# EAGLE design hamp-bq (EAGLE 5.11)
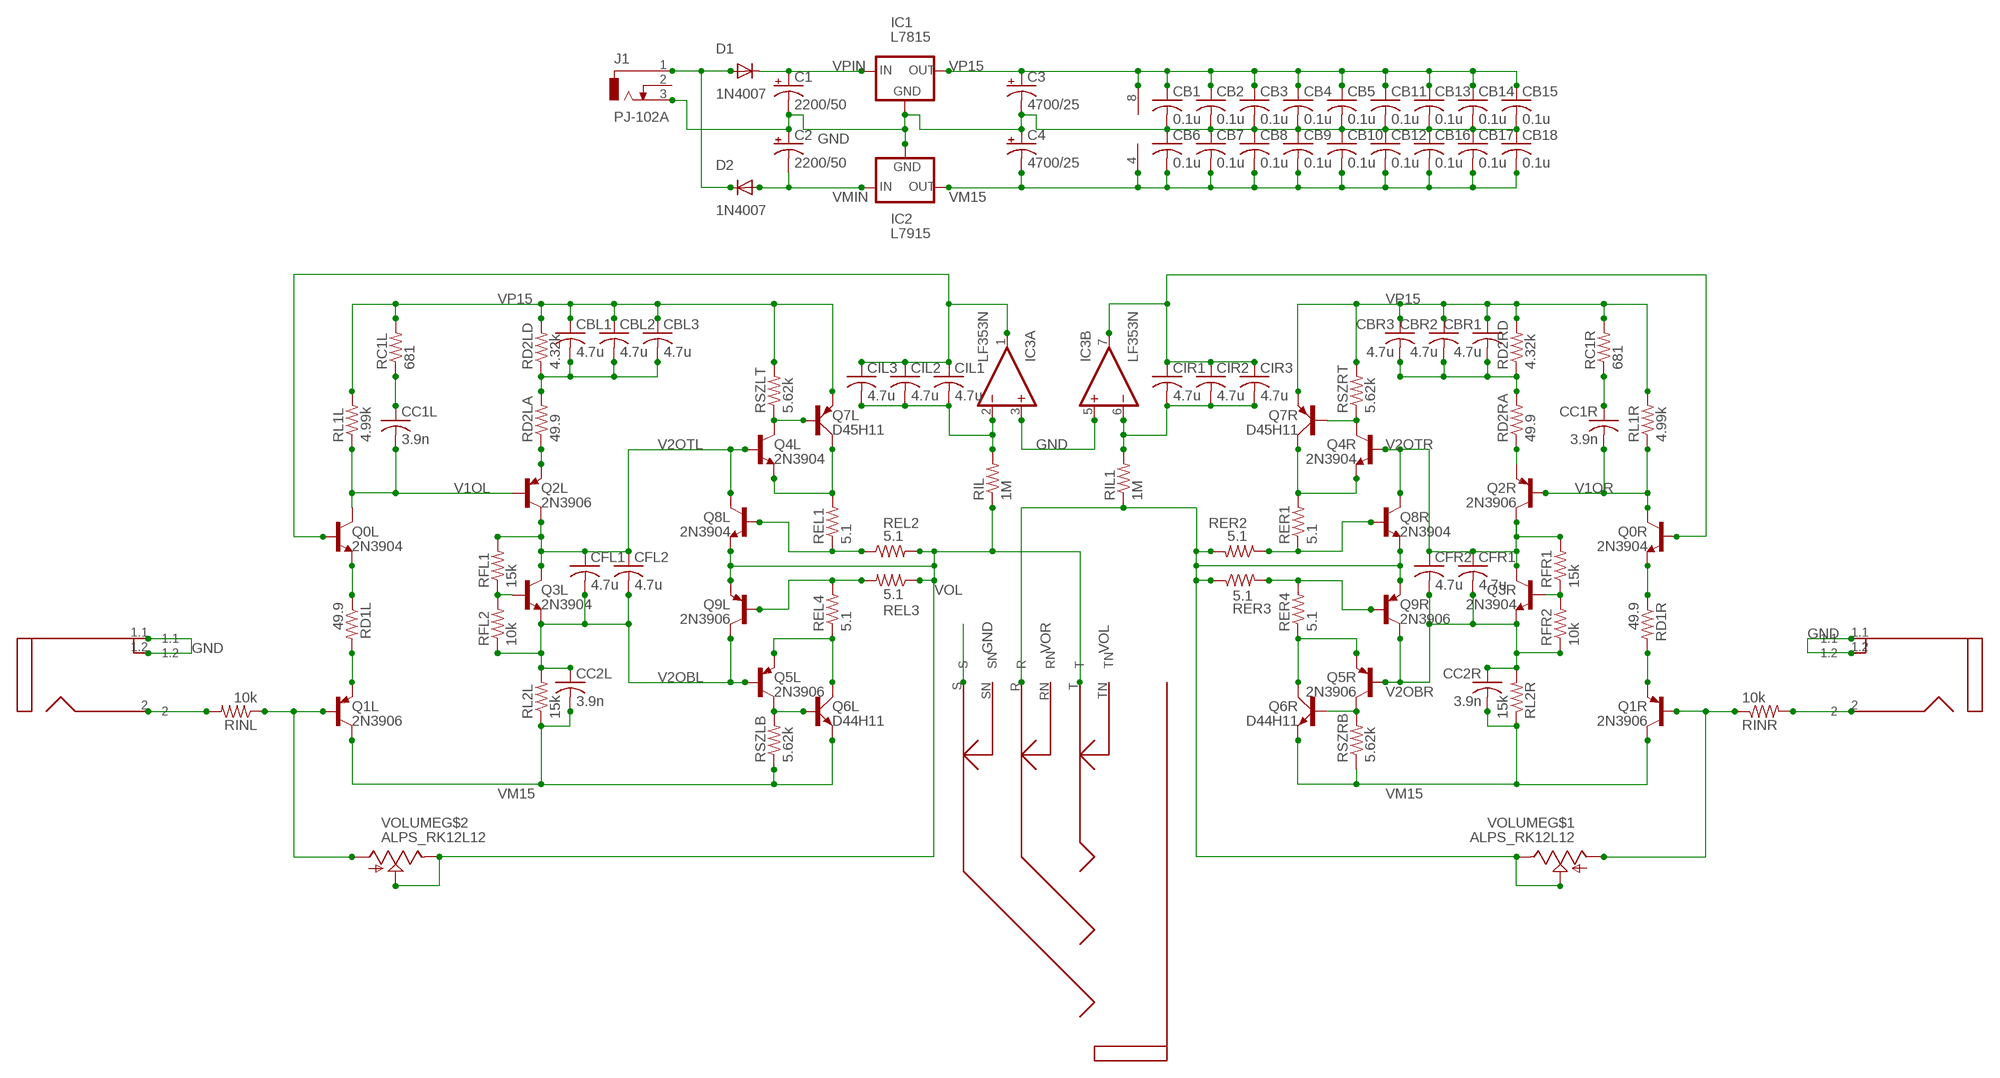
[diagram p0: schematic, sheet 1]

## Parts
C1  2200/50  CPOL-USE7.5-16  [E7,5-16]
C2  2200/50  CPOL-USE7.5-16  [E7,5-16]
C3  4700/25  CPOL-USE7.5-16  [E7,5-16]
C4  4700/25  CPOL-USE7.5-16  [E7,5-16]
CB1  0.1u  C-US025-025X050  [C025-025X050]
CB2  0.1u  C-US025-025X050  [C025-025X050]
CB3  0.1u  C-US025-025X050  [C025-025X050]
CB4  0.1u  C-US025-025X050  [C025-025X050]
CB5  0.1u  C-US025-025X050  [C025-025X050]
CB6  0.1u  C-US025-025X050  [C025-025X050]
CB7  0.1u  C-US025-025X050  [C025-025X050]
CB8  0.1u  C-US025-025X050  [C025-025X050]
CB9  0.1u  C-US025-025X050  [C025-025X050]
CB10  0.1u  C-US025-025X050  [C025-025X050]
CB11  0.1u  C-US025-025X050  [C025-025X050]
CB12  0.1u  C-US025-025X050  [C025-025X050]
CB13  0.1u  C-US025-025X050  [C025-025X050]
CB14  0.1u  C-US025-025X050  [C025-025X050]
CB15  0.1u  C-US025-025X050  [C025-025X050]
CB16  0.1u  C-US025-025X050  [C025-025X050]
CB17  0.1u  C-US025-025X050  [C025-025X050]
CB18  0.1u  C-US025-025X050  [C025-025X050]
CBL1  4.7u  C-US050-035X075  [C050-035X075]
CBL2  4.7u  C-US050-035X075  [C050-035X075]
CBL3  4.7u  C-US050-035X075  [C050-035X075]
CBR1  4.7u  C-US050-035X075  [C050-035X075]
CBR2  4.7u  C-US050-035X075  [C050-035X075]
CBR3  4.7u  C-US050-035X075  [C050-035X075]
CC1L  3.9n  C-US025-025X050  [C025-025X050]
CC1R  3.9n  C-US025-025X050  [C025-025X050]
CC2L  3.9n  C-US025-025X050  [C025-025X050]
CC2R  3.9n  C-US025-025X050  [C025-025X050]
CFL1  4.7u  C-US050-035X075  [C050-035X075]
CFL2  4.7u  C-US050-035X075  [C050-035X075]
CFR1  4.7u  C-US050-035X075  [C050-035X075]
CFR2  4.7u  C-US050-035X075  [C050-035X075]
CIL1  4.7u  C-US050-035X075  [C050-035X075]
CIL2  4.7u  C-US050-035X075  [C050-035X075]
CIL3  4.7u  C-US050-035X075  [C050-035X075]
CIR1  4.7u  C-US050-035X075  [C050-035X075]
CIR2  4.7u  C-US050-035X075  [C050-035X075]
CIR3  4.7u  C-US050-035X075  [C050-035X075]
D1  1N4007  1N4004  [DO41-10]
D2  1N4007  1N4004  [DO41-10]
IC1  L7815  78XXS  [78XXS]
IC2  L7915  79XXS  [79XXS]
IC3  LF353N  [DIL08]
J1  PJ-102A  DCJ0303  [DCJ0303]
Q0L  2N3904  [TO92]
Q0R  2N3904  [TO92]
Q1L  2N3906  [TO92]
Q1R  2N3906  [TO92]
Q2L  2N3906  [TO92]
Q2R  2N3906  [TO92]
Q3L  2N3904  [TO92]
Q3R  2N3904  [TO92]
Q4L  2N3904  [TO92]
Q4R  2N3904  [TO92]
Q5L  2N3906  [TO92]
Q5R  2N3906  [TO92]
Q6L  D44H11  MJE3055  [TO220AV]
Q6R  D44H11  MJE3055  [TO220AV]
Q7L  D45H11  MJE2955  [TO220AV]
Q7R  D45H11  MJE2955  [TO220AV]
Q8L  2N3904  [TO92]
Q8R  2N3904  [TO92]
Q9L  2N3906  [TO92]
Q9R  2N3906  [TO92]
RC1L  681  R-US_0309/V  [0309V]
RC1R  681  R-US_0309/V  [0309V]
RD1L  49.9  R-US_0309/V  [0309V]
RD1R  49.9  R-US_0309/V  [0309V]
RD2LA  49.9  R-US_0309/V  [0309V]
RD2LD  4.32k  R-US_0309/V  [0309V]
RD2RA  49.9  R-US_0309/V  [0309V]
RD2RD  4.32k  R-US_0309/V  [0309V]
REL1  5.1  R-US_0309/V  [0309V]
REL2  5.1  R-US_0309/V  [0309V]
REL3  5.1  R-US_0309/V  [0309V]
REL4  5.1  R-US_0309/V  [0309V]
RER1  5.1  R-US_0309/V  [0309V]
RER2  5.1  R-US_0309/V  [0309V]
RER3  5.1  R-US_0309/V  [0309V]
RER4  5.1  R-US_0309/V  [0309V]
RFL1  15k  R-US_0309/V  [0309V]
RFL2  10k  R-US_0309/V  [0309V]
RFR1  15k  R-US_0309/V  [0309V]
RFR2  10k  R-US_0309/V  [0309V]
RIL  1M  R-US_0309/V  [0309V]
RIL1  1M  R-US_0309/V  [0309V]
RINL  10k  R-US_0309/V  [0309V]
RINR  10k  R-US_0309/V  [0309V]
RL1L  4.99k  R-US_0309/V  [0309V]
RL1R  4.99k  R-US_0309/V  [0309V]
RL2L  15k  R-US_0309/V  [0309V]
RL2R  15k  R-US_0309/V  [0309V]
RSZLB  5.62k  R-US_0309/V  [0309V]
RSZLT  5.62k  R-US_0309/V  [0309V]
RSZRB  5.62k  R-US_0309/V  [0309V]
RSZRT  5.62k  R-US_0309/V  [0309V]
U$1  NJ6H?D2  [NMJ6H?D2]
U$2  RCA-VERT  [RCA]
U$3  RCA-VERT  [RCA]
VOLUME  ALPS_RK12L12  [RK12L12C]

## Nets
GND [supply]: C1.- C2.+ C3.- C4.+ CB1.2 CB2.2 CB3.2 CB4.2 CB5.2 CB6.1 CB7.1 CB8.1 CB9.1 CB10.1 CB11.2 CB12.1 CB13.2 CB14.2 CB15.2 CB16.1 CB17.1 CB18.1 IC1.GND IC2.GND IC3.3(A:+IN) IC3.5(B:+IN) J1.3 U$1.S U$2.1.1 U$2.1.2 U$3.1.1 U$3.1.2
N$1 [supply]: D1.A D2.C J1.1
N$6: Q0L.3(E) RD1L.1
N$7: Q1L.3(E) RD1L.2
N$8: CC1L.1 RC1L.1
N$9: CIL1.2 CIL2.2 CIL3.2 IC3.2(A:-IN) RIL.2
N$10: Q1L.2(B) RINL.1 VOLUME.2.1(A)
N$11: Q4L.1(C) Q7L.B RSZLT.1
N$12: Q5L.1(C) Q6L.B RSZLB.2
N$13: CBL1.2 CBL2.2 CBL3.2 RD2LA.2 RD2LD.1
N$14: Q2L.3(E) RD2LA.1
N$15: Q3L.2(B) RFL1.1 RFL2.2
N$16: CIL1.1 CIL2.1 CIL3.1 IC3.1(A:OUT) Q0L.2(B)
N$17: RINL.2 U$2.2
N$18: Q9L.2(B) REL3.2 REL4.2
N$19 [power]: Q5L.3(E) Q6L.C REL4.1
N$20 [power]: Q4L.3(E) Q7L.C REL1.2
N$21: Q8L.2(B) REL1.1 REL2.1
N$22: CIR1.1 CIR2.1 CIR3.1 IC3.7(B:OUT) Q0R.2(B)
N$23: CIR1.2 CIR2.2 CIR3.2 IC3.6(B:-IN) RIL1.2
N$25 [power]: Q5R.3(E) Q6R.C RER4.1
N$26: Q9R.2(B) RER3.2 RER4.2
N$27: CBR1.2 CBR2.2 CBR3.2 RD2RA.2 RD2RD.1
N$28: Q8R.2(B) RER1.1 RER2.1
N$29 [power]: Q4R.3(E) Q7R.C RER1.2
N$30: Q4R.1(C) Q7R.B RSZRT.1
N$31: Q0R.3(E) RD1R.1
N$32: Q2R.3(E) RD2RA.1
N$33: Q1R.3(E) RD1R.2
N$34: CC1R.1 RC1R.1
N$35: Q5R.1(C) Q6R.B RSZRB.2
N$37: Q3R.2(B) RFR1.1 RFR2.2
N$38: Q1R.2(B) RINR.1 VOLUME.1.1(A)
N$39: RINR.2 U$3.2
V1OL: CC1L.2 Q0L.1(C) Q2L.2(B) RL1L.1
V1OR: CC1R.2 Q0R.1(C) Q2R.2(B) RL1R.1
V2OBL: CC2L.1 CFL1.2 CFL2.2 Q3L.3(E) Q5L.2(B) Q9L.1(C) RFL2.1 RL2L.2
V2OBR: CC2R.1 CFR1.2 CFR2.2 Q3R.3(E) Q5R.2(B) Q9R.1(C) RFR2.1 RL2R.2
V2OTL: CFL1.1 CFL2.1 Q2L.1(C) Q3L.1(C) Q4L.2(B) Q8L.1(C) RFL1.2
V2OTR: CFR1.1 CFR2.1 Q2R.1(C) Q3R.1(C) Q4R.2(B) Q8R.1(C) RFR1.2
VM15 [supply]: C4.- CB6.2 CB7.2 CB8.2 CB9.2 CB10.2 CB12.2 CB16.2 CB17.2 CB18.2 CC2L.2 CC2R.2 IC2.OUT IC3.4(P:V-) Q1L.1(C) Q1R.1(C) Q6L.E Q6R.E RL2L.1 RL2R.1 RSZLB.1 RSZRB.1
VMIN [supply]: C2.- D2.A IC2.IN
VOL [power]: Q8L.3(E) Q9L.3(E) REL2.2 REL3.1 RIL.1 U$1.T VOLUME.2.2(S) VOLUME.2.3(E)
VOR [power]: Q8R.3(E) Q9R.3(E) RER2.2 RER3.1 RIL1.1 U$1.R VOLUME.1.2(S) VOLUME.1.3(E)
VP15 [supply]: C3.+ CB1.1 CB2.1 CB3.1 CB4.1 CB5.1 CB11.1 CB13.1 CB14.1 CB15.1 CBL1.1 CBL2.1 CBL3.1 CBR1.1 CBR2.1 CBR3.1 IC1.OUT IC3.8(P:V+) Q7L.E Q7R.E RC1L.2 RC1R.2 RD2LD.2 RD2RD.2 RL1L.2 RL1R.2 RSZLT.2 RSZRT.2
VPIN [supply]: C1.+ D1.C IC1.IN
Unconnected: J1.2 U$1.RN U$1.SN U$1.TN

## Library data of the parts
C1-C4 = rcl:CPOL-US: POLARIZED CAPACITOR, American symbol
CB1-CB18 CBL1-CBL3 CBR1-CBR3 CC1L CC1R CC2L CC2R CFL1 CFL2 CFR1 CFR2 CIL1-CIL3 CIR1-CIR3 = rcl:C-US: CAPACITOR, American symbol
D1 D2 = diode:1N4004: DIODE
IC1 = v-reg:78XXS: VOLTAGE REGULATOR
IC2 = v-reg:79XXS: VOLTAGE REGULATOR
IC3 = linear:LF353: OP AMP
J1 = con-jack:DCJ0303: DC POWER JACK Source: DCJ0303.pdf; OC_FARNELL: unknown; OC_NEWARK: unknown
Q0L Q0R Q3L Q3R Q4L Q4R Q8L Q8R = transistor:2N3904: NPN TRANSISTOR
Q1L Q1R Q2L Q2R Q5L Q5R Q9L Q9R = transistor-pnp:2N3906: PNP Transistor
Q6L Q6R = transistor-power:MJE3055: NPN TRANSISTOR
Q7L Q7R = transistor-power:MJE2955: PNP TRANSISTOR
RC1L RC1R RD1L RD1R RD2LA RD2LD RD2RA RD2RD REL1-REL4 RER1-RER4 RFL1 RFL2 RFR1 RFR2 RIL RIL1 RINL RINR RL1L RL1R RL2L RL2R RSZLB RSZLT RSZRB RSZRT = rcl:R-US_: RESISTOR, American symbol
U$1 = con-neutrik_ag:NJ6: Neutrik NJ6* stereo 1/4" audio jack
U$2 U$3 = con-cui:RCA-VERT
VOLUME = pot:ALPS_RK12L12

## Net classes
0 default: width 0.406 mm, clearance 0.203 mm
1 power: width 0.762 mm, clearance 0.381 mm
2 supply: width 1.27 mm, clearance 0.381 mm

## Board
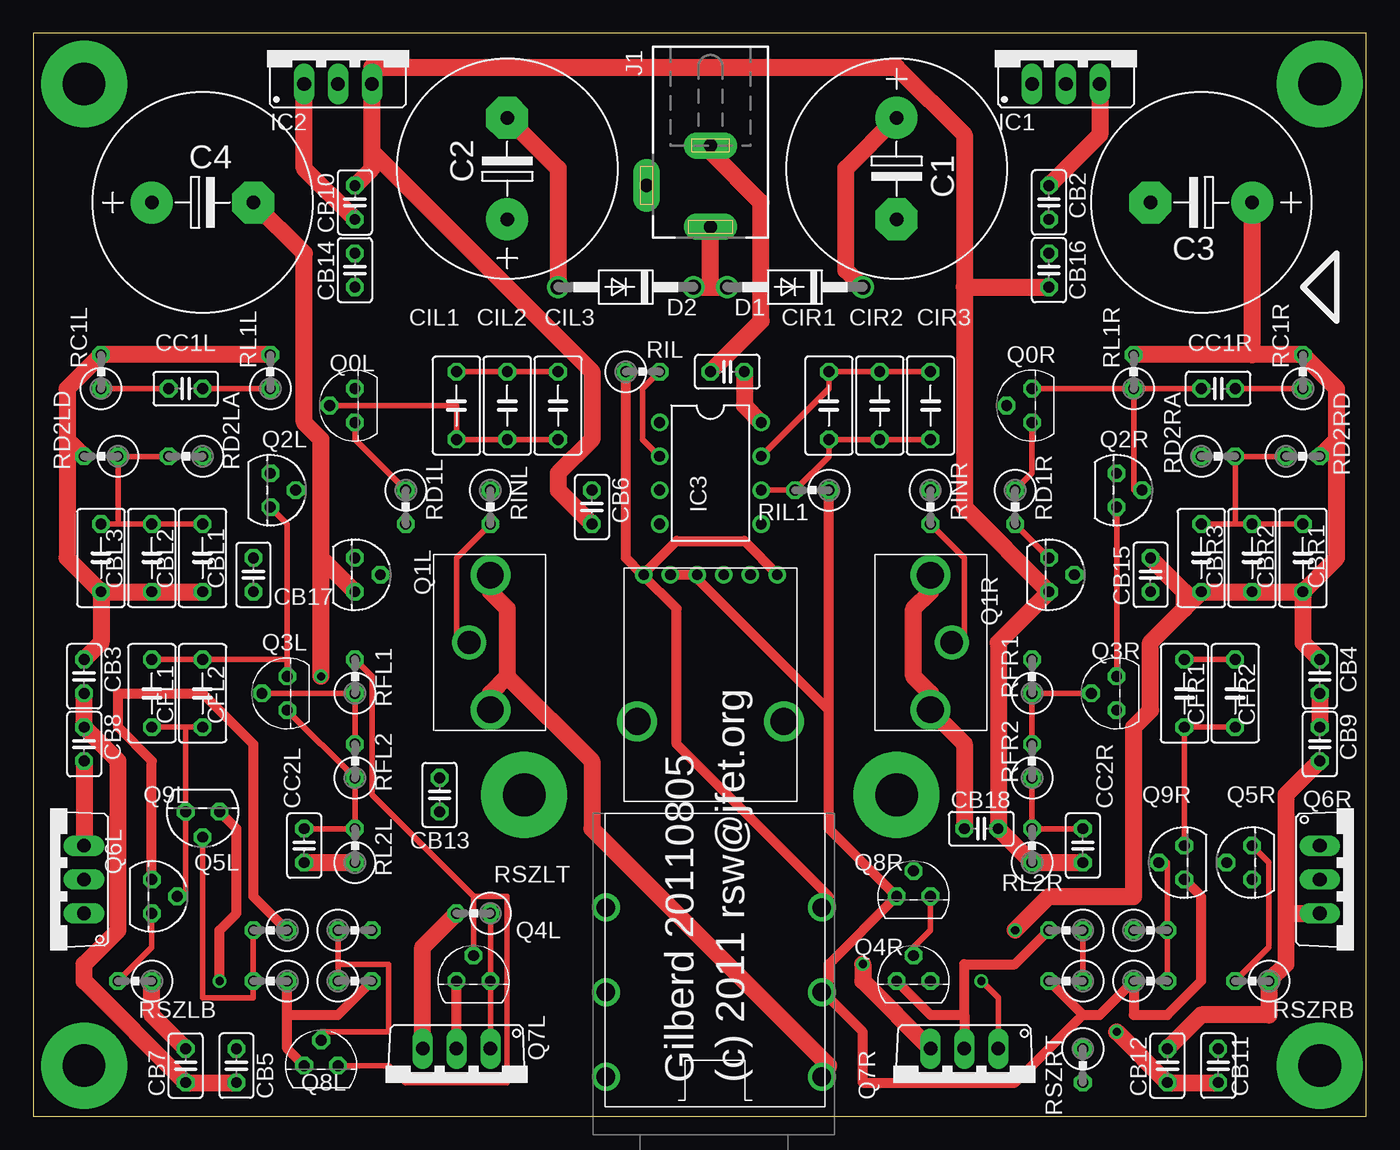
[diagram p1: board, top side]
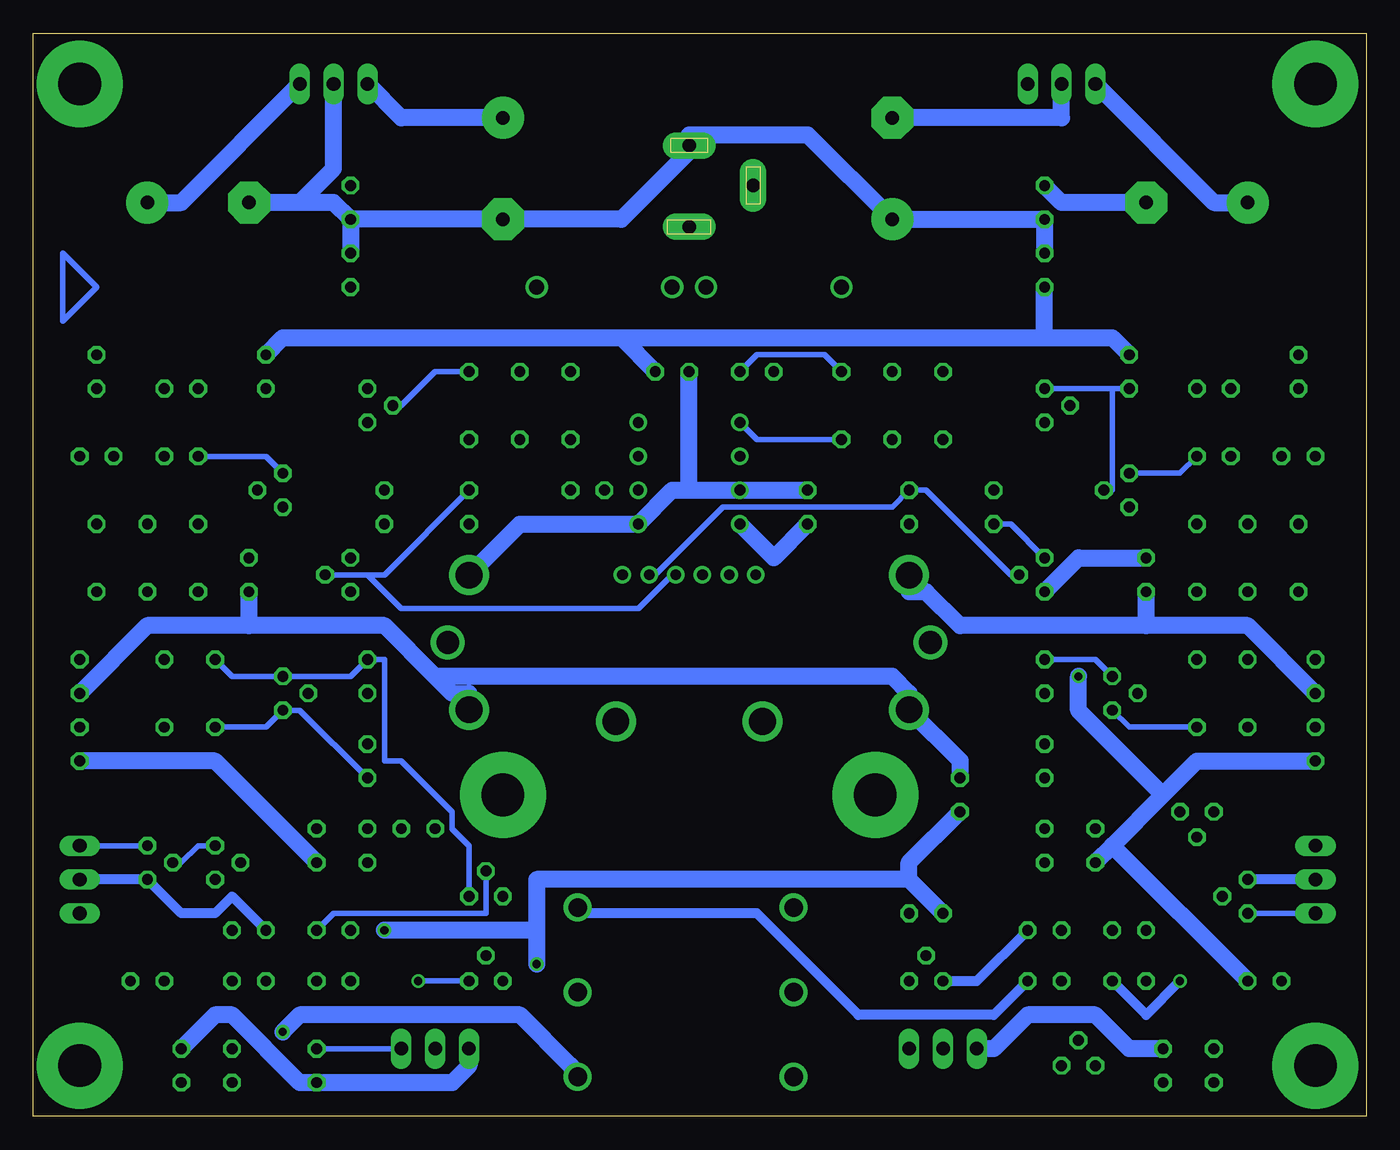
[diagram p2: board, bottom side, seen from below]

Size 100 x 81.27 mm. Coordinates in mm from the lower left corner, seen from the top.
Outline: 0,0 100,0 100,81.27 0,81.27 0,0
Copper layers (1*16): Top 0.035mm / dielectric 1.5mm / Bottom 0.035mm
Design rules "default": minimum track width 10mil, minimum drill 24mil, track to track 8mil, track to pad 8mil, pad to pad 8mil, via to via 8mil, smd to smd 8mil, copper to edge 40mil, drill to drill 8mil, minimum pad ring 10mil, minimum via ring 8mil, stop-mask expansion 4mil, vias tented up to drill 0mil, thermal gap 10mil

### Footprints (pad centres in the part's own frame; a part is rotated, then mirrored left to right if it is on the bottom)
E7,5-16 = drill 1.016 pad 3.15 round: + -3.81,0 | drill 1.016 pad 3.15 octagon: - 3.81,0
C025-025X050 = drill 0.813 octagon: 1 -1.27,0; 2 1.27,0
C050-035X075 = drill 0.813 octagon: 1 -2.54,0; 2 2.54,0
DO41-10 = drill 1.118 round: A 5.08,0; C -5.08,0
78XXS = drill 1.016 long: GND 0,-2.54; IN -2.54,-2.54; OUT 2.54,-2.54
79XXS = drill 1.016 long: GND -2.54,-2.54; IN 0,-2.54; OUT 2.54,-2.54
DIL08 = drill 0.813 pad 1.27 round: 1 -3.81,-3.81; 2 -1.27,-3.81; 3 1.27,-3.81; 4 3.81,-3.81; 5 3.81,3.81; 6 1.27,3.81; 7 -1.27,3.81; 8 -3.81,3.81
DCJ0303 = drill 1 pad 2 long: 1 0,3.1; 2 4.8,0; 3 0,-3
TO92 = drill 0.813 octagon: 1 1.27,0; 2 0,1.905; 3 -1.27,0
TO220AV = drill 1.016 long: B -2.54,-2.54; C 0,-2.54; E 2.54,-2.54
0309V = drill 0.813 octagon: 1 -1.27,0; 2 1.27,0
NMJ6H?D2 = drill 1.4 round: R 17.25,10.6; RN 1.05,10.6; S 17.25,4.25; SN 1.05,4.25; T 17.25,16.95; TN 1.05,16.95
RCA = drill 2 round: 1.1 -5.05,0; 1.2 5.05,0 | drill 1.7 round: 2 0,1.6
RK12L12C = drill 0.8 round: 1.1 -1,0; 1.2 1,0; 1.3 3,0; 2.1 -3,0; 2.2 -5,0; 2.3 5,0 | drill 2 round: CASE1 -5.5,11; CASE2 5.5,11

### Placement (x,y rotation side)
C1  64.77,71.12 270 top
C2  35.56,71.12 90 top
C3  87.63,68.58 180 top
C4  12.7,68.58 0 top
CB1  52.07,55.88 180 top
CB2  76.2,68.58 270 top
CB3  3.81,33.02 270 top
CB4  96.52,33.02 270 top
CB5  15.24,3.81 270 top
CB6  41.91,45.72 270 top
CB7  11.43,3.81 90 top
CB8  3.81,27.94 270 top
CB9  96.52,27.94 270 top
CB10  24.13,68.58 90 top
CB11  88.9,3.81 270 top
CB12  85.09,3.81 90 top
CB13  30.48,24.13 90 top
CB14  24.13,63.5 90 top
CB15  83.82,40.64 270 top
CB16  76.2,63.5 270 top
CB17  16.51,40.64 90 top
CB18  71.12,21.59 0 top
CBL1  12.7,41.91 90 top
CBL2  8.89,41.91 90 top
CBL3  5.08,41.91 90 top
CBR1  95.25,41.91 90 top
CBR2  91.44,41.91 90 top
CBR3  87.63,41.91 90 top
CC1L  11.43,54.61 0 top
CC1R  88.9,54.61 180 top
CC2L  20.32,20.32 270 top
CC2R  78.74,20.32 270 top
CFL1  8.89,31.75 270 top
CFL2  12.7,31.75 270 top
CFR1  86.36,31.75 270 top
CFR2  90.17,31.75 270 top
CIL1  31.75,53.34 90 top
CIL2  35.56,53.34 90 top
CIL3  39.37,53.34 90 top
CIR1  59.69,53.34 270 top
CIR2  63.5,53.34 270 top
CIR3  67.31,53.34 270 top
D1  57.15,62.23 180 top
D2  44.45,62.23 180 top
IC1  77.47,80.01 0 top
IC2  22.86,80.01 0 top
IC3  50.8,48.26 270 top
J1  50.8,69.85 180 top
Q0L  24.13,53.34 90 top
Q0R  74.93,53.34 90 top
Q1L  24.13,40.64 270 top
Q1R  76.2,40.64 270 top
Q2L  17.78,46.99 270 top
Q2R  81.28,46.99 270 top
Q3L  19.05,31.75 90 top
Q3R  81.28,31.75 90 top
Q4L  33.02,10.16 0 top
Q4R  66.04,10.16 0 top
Q5L  8.89,16.51 270 top
Q5R  91.44,19.05 90 top
Q6L  1.27,17.78 90 top
Q6R  99.06,17.78 270 top
Q7L  31.75,2.54 180 top
Q7R  69.85,2.54 180 top
Q8L  21.59,3.81 0 top
Q8R  66.04,16.51 0 top
Q9L  12.7,22.86 180 top
Q9R  86.36,19.05 90 top
RC1L  5.08,55.88 90 top
RC1R  95.25,55.88 90 top
RD1L  27.94,45.72 270 top
RD1R  73.66,45.72 270 top
RD2LA  11.43,49.53 180 top
RD2LD  5.08,49.53 180 top
RD2RA  88.9,49.53 0 top
RD2RD  95.25,49.53 0 top
REL1  24.13,13.97 0 top
REL2  24.13,10.16 0 top
REL3  17.78,10.16 180 top
REL4  17.78,13.97 180 top
RER1  77.47,13.97 180 top
RER2  77.47,10.16 180 top
RER3  83.82,10.16 0 top
RER4  83.82,13.97 0 top
RFL1  24.13,33.02 90 top
RFL2  24.13,26.67 90 top
RFR1  74.93,33.02 90 top
RFR2  74.93,26.67 90 top
RIL  45.72,55.88 0 top
RIL1  58.42,46.99 180 top
RINL  34.29,45.72 270 top
RINR  67.31,45.72 270 top
RL1L  17.78,55.88 90 top
RL1R  82.55,55.88 90 top
RL2L  24.13,20.32 90 top
RL2R  74.93,20.32 90 top
RSZLB  7.62,10.16 180 top
RSZLT  33.02,15.24 180 top
RSZRB  91.44,10.16 180 top
RSZRT  78.74,3.81 270 top
U$1  41.91,-1.27 0 top
U$2  34.29,35.56 90 top
U$3  67.31,35.56 270 top
VOLUME  50.8,40.64 180 top

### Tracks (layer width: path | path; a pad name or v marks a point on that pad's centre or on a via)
GND  (via drill 0.61)
  Top 1.27: CB11.2 CB12.1 v81.28,6.35 | CB5.2 CB7.1 3.81,10.16 3.81,11.43 6.35,13.97 6.35,26.67 CB8.1 CB3.2 | 35.56,33.02 34.29,31.75 U$2.1.1 | 35.56,33.02 35.56,38.1 34.29,39.37 U$2.1.2 | 35.56,33.02 41.91,26.67 41.91,21.59 59.69,3.81 U$1.S | CB4.2 CB9.1 | U$3.1.1 67.31,39.37 66.04,38.1 66.04,33.02 67.31,31.75 U$3.1.2 69.85,27.97 CB18.1 | CB10.1 20.32,71.12 IC2.GND | CB1.2 54.61,59.69 54.61,68.58 50.8,72.39 J1.3
  Bottom 1.27: v81.28,6.35 80.01,7.62 63.5,7.62 59.69,3.81 U$1.S | CB3.2 8.89,36.83 16.51,36.83 | 16.51,36.83 30.48,36.83 33.02,39.37 34.29,39.37 U$2.1.2 | CB4.2 91.44,36.83 83.82,36.83 | 83.82,36.83 73.66,36.83 69.85,33.02 | 69.85,33.02 68.58,31.75 67.31,31.75 U$3.1.2 | CB6.1 IC3.3 50.8,46.99 | 50.8,46.99 52.07,46.99 IC3.5 63.5,44.45 67.31,40.64 U$3.1.1 | 50.8,46.99 CB1.2 | IC2.GND 11.43,68.58 C4.+ | CB2.2 77.47,68.58 80.01,68.58 | 80.01,68.58 C3.- | IC1.GND 77.47,71.12 80.01,68.58 | CB2.2 C1.- 55.88,67.31 50.8,72.39 J1.3 50.8,73.66 41.91,73.66 C2.+ CB10.1 CB14.2 | 69.85,33.02 35.56,33.02 34.29,31.75 U$2.1.1 30.48,26.7 CB13.2 | CB2.2 CB16.1 | 16.51,36.83 CB17.1 | 83.82,36.83 CB15.2
N$1
  Top 1.27: 50.8,62.23 D1.A | D2.C 50.8,62.23 | 50.8,62.23 J1.1
N$2  (via drill 3.2 pad 6.45)
  other vias: 3.81,77.47
N$3  (via drill 3.2 pad 6.45)
  other vias: 36.83,24.13
N$4  (via drill 3.2 pad 6.45)
  other vias: 96.52,3.81
N$5  (via drill 3.2 pad 6.45)
  other vias: 3.81,3.81
N$6
  Top 0.406: RD1L.1 24.13,50.8 Q0L.3
N$7
  Bottom 0.406: Q1L.3 26.67,44.45 RD1L.2
N$8
  Top 0.406: RC1L.1 CC1L.1
N$9
  Top 0.406: IC3.2 45.72,50.8 45.72,54.61 RIL.2 | CIL1.2 CIL2.2 CIL3.2
  Bottom 0.406: RIL.2 45.72,57.15 40.64,57.15 CIL3.2
N$10
  Bottom 0.406: VOLUME.2.1 53.34,40.64 48.26,45.72 35.56,45.72 RINL.1 33.02,46.99 26.67,40.64 Q1L.2
N$11
  Top 0.406: RSZLT.1 Q4L.1 Q7L.B
N$12
  Top 0.406: RSZLB.2 8.89,12.7 Q5L.1
  Bottom 0.406: Q5L.1 Q6L.B
N$13
  Top 0.406: RD2LA.2 RD2LD.1 6.35,44.45 | 6.35,44.45 CBL2.2 CBL1.2 | CBL3.2 6.35,44.45
N$14
  Bottom 0.406: RD2LA.1 13.97,48.26 Q2L.3
N$15
  Top 0.406: Q3L.2 RFL1.1 RFL2.2
N$16
  Top 0.406: CIL3.1 CIL2.1 CIL1.1 31.75,53.34 Q0L.2
  Bottom 0.406: IC3.1 45.72,50.8 CIL3.1
N$17
  Top 0.406: RINL.2 31.75,41.91 31.75,35.56 U$2.2
N$18
  Top 0.406: REL4.2 REL3.2 16.51,8.89 12.7,8.89 Q9L.2
N$19
  Top 0.762: REL4.1 16.51,16.51 16.51,27.94 12.7,31.75 6.35,31.75 6.35,29.21 8.89,26.67 Q5L.3
  Bottom 0.762: Q6L.C Q5L.3
N$20
  Top 0.762: Q7L.C Q4L.3
  Bottom 0.762: REL1.2 29.21,10.16 Q4L.3
N$21
  Top 0.406: 22.86,11.43 26.67,11.43 26.67,6.35 21.59,6.35 Q8L.2 | 22.86,11.43 REL2.1 | 22.86,11.43 REL1.1
N$22
  Top 0.406: IC3.7 59.69,54.61 CIR1.1 CIR2.1 CIR3.1
  Bottom 0.406: CIR3.1 69.85,55.88 72.39,53.34 Q0R.2
N$23
  Top 0.406: IC3.6 RIL1.2 59.69,49.53 CIR1.2 CIR2.2 CIR3.2
N$24  (via drill 3.2 pad 6.45)
  other vias: 64.77,24.13
N$25
  Bottom 0.762: RER4.1 85.09,16.51 86.36,15.24 88.9,15.24 Q5R.3 Q6R.C
N$26
  Top 0.406: RER3.2 RER4.2 85.09,19.05 Q9R.2
N$27
  Top 0.406: RD2RD.1 RD2RA.2 90.17,44.45 | 90.17,44.45 CBR2.2 CBR1.2 | CBR3.2 90.17,44.45
N$28
  Top 0.406: RER1.1 RER2.1
  Bottom 0.406: RER1.1 77.47,15.24 66.04,15.24 Q8R.2
N$29
  Top 0.762: Q4R.3 67.31,7.62 69.85,7.62 | 69.85,7.62 Q7R.C | RER1.2 73.66,11.43 69.85,11.43 69.85,7.62
N$30  (via drill 0.61)
  Top 0.406: v71.12,10.16 72.39,8.89 Q7R.B
  Bottom 0.406: Q7R.B RSZRT.1 | Q4R.1 v71.12,10.16
N$31
  Top 0.406: RD1R.1 74.93,48.26 Q0R.3
N$32
  Bottom 0.406: Q2R.3 82.55,49.53 RD2RA.1
N$33
  Top 0.406: Q1R.3 RD1R.2
N$34
  Top 0.406: CC1R.1 RC1R.1
N$35
  Top 0.406: RSZRB.2 92.71,12.7 92.71,19.05 Q5R.1
  Bottom 0.406: Q5R.1 Q6R.B
N$36
  Bottom 0.406: 95.25,62.23 97.79,64.77 97.79,59.69 95.25,62.23
N$37
  Top 0.406: RFR2.2 RFR1.1 Q3R.2
N$38
  Bottom 0.406: 74.93,40.64 72.39,38.1 54.61,38.1 52.07,40.64 VOLUME.1.1 | 74.93,40.64 Q1R.2 | RINR.1 73.66,40.64 74.93,40.64
N$39
  Top 0.406: RINR.2 69.85,41.91 69.85,35.56 U$3.2
N$40
  Top 0.406: 95.25,62.23 97.79,64.77 97.79,59.69 95.25,62.23
NH1  (via drill 3.2 pad 6.45)
  other vias: 96.52,77.47
V1OL
  Top 0.406: RL1L.1 CC1L.2
  Bottom 0.406: 19.05,54.61 19.05,46.99 Q2L.2 | 19.05,54.61 RL1L.1 | 19.05,54.61 Q0L.1
V1OR
  Top 0.406: RL1R.1 Q0R.1 | RL1R.1 82.55,46.99 Q2R.2 | RL1R.1 CC1R.2
V2OBL
  Top 0.406: CC2L.1 RL2L.2 RFL2.1 Q3L.3 | Q5L.2 11.43,16.51 Q9L.1 11.43,29.21 | 11.43,29.21 CFL2.2 | 11.43,29.21 CFL1.2
  Bottom 0.406: Q3L.3 17.78,29.21 CFL2.2
V2OBR
  Top 0.406: RFR2.1 RL2R.2 CC2R.1 | CFR2.2 CFR1.2 Q9R.1
  Bottom 0.406: Q9R.1 87.63,20.32 88.9,19.05 Q5R.2 | CFR1.2 82.55,29.21 Q3R.3 80.01,30.48 RFR2.1
V2OTL
  Top 0.406: Q8L.1 26.67,3.81 27.94,2.54 35.56,2.54 35.56,16.51 33.02,16.51 | 33.02,16.51 Q4L.2 | CFL1.1 CFL2.1 19.05,34.29 | Q2L.1 19.05,44.45 19.05,34.29 | Q3L.1 19.05,34.29 | 33.02,16.51 25.4,24.13 25.4,33.02 RFL1.2
  Bottom 0.406: Q3L.1 20.32,34.29 RFL1.2
V2OTR
  Top 0.406: Q8R.1 67.31,13.97 66.04,12.7 Q4R.2 | CFR1.1 CFR2.1 | Q3R.1 Q2R.1
  Bottom 0.406: CFR1.1 85.09,33.02 Q3R.1 76.2,33.02 RFR1.2 73.66,34.29 73.66,26.67 72.39,26.67 68.58,22.86 68.58,21.59 67.31,20.32 Q8R.1
VM15  (via drill 0.61)
  Top 1.27: CC2R.2 RL2R.1 CB18.2 72.39,35.56 Q1R.1 69.85,45.72 69.85,62.23 | CB12.2 87.63,7.62 92.71,7.62 RSZRB.1 93.98,11.43 93.98,15.24 | CB9.2 93.98,24.13 93.98,15.24 | 93.98,15.24 Q6R.E | CB10.2 25.4,71.12 25.4,72.39 | 25.4,72.39 IC2.OUT 25.4,78.74 64.77,78.74 69.85,73.66 69.85,62.23 | CB6.2 39.37,46.99 39.37,48.26 41.91,50.8 41.91,55.88 25.4,72.39 | CB7.2 8.89,7.62 RSZLB.1 | CC2L.2 RL2L.1 | CB8.2 Q6L.E | 21.59,41.91 Q1L.1 | 21.59,41.91 21.59,50.8 20.32,52.07 20.32,64.77 C4.- | v21.59,33.02 21.59,41.91 | 69.85,62.23 CB16.2
  Bottom 1.27: CC2R.2 86.36,26.67 CB9.2 | CB6.2 44.45,41.91 IC3.4 | 15.24,24.13 12.7,26.67 CB8.2 | 19.05,20.32 15.24,24.13 | 19.05,20.32 CC2L.2 | RSZLB.1 19.05,20.32 | 15.24,24.13 21.59,30.48 v21.59,33.02 | CB10.2 22.86,68.58 C4.- | CB17.2 21.59,41.91 Q1L.1
VMIN
  Top 1.27: D2.A 39.37,71.12 C2.-
  Bottom 1.27: IC2.IN 22.86,74.93 C2.-
VOL  (via drill 0.61)
  Top 0.762: Q8L.3 19.05,5.08 19.05,7.62 | 19.05,7.62 REL3.1 | REL2.2 22.86,7.62 19.05,7.62 | Q9L.3 15.24,21.59 15.24,15.24 13.97,13.97 v13.97,10.16 | 45.72,40.64 44.45,41.91 RIL.1 | 45.72,40.64 48.26,43.18 53.34,43.18 55.88,40.64 VOLUME.2.2 | 45.72,40.64 48.26,38.1 48.26,27.94 59.69,16.51 U$1.T | 45.72,40.64 VOLUME.2.3
  Bottom 0.762: v13.97,10.16 16.51,7.62 REL3.1 | REL2.2 27.94,7.62 38.1,7.62 45.72,15.24 58.42,15.24 U$1.T
VOR
  Top 0.762: 78.74,7.62 RER2.2 | 78.74,7.62 80.01,7.62 RER3.1 82.55,7.62 85.09,7.62 87.63,10.16 87.63,16.51 Q9R.3 | 49.53,40.64 VOLUME.1.3 | 59.69,30.48 59.69,21.59 Q8R.3 59.69,11.43 59.69,10.16 U$1.R 59.69,8.89 62.23,6.35 62.23,2.54 73.66,2.54 78.74,7.62 | 59.69,30.48 RIL1.1 | 59.69,30.48 49.53,40.64 | 49.53,40.64 VOLUME.1.2
VP15  (via drill 0.61)
  Top 1.27: RSZLT.2 29.21,12.7 Q7L.E | Q7R.E 62.23,10.16 v62.23,11.43 | CB3.1 5.08,35.56 CBL3.1 | CBL3.1 CBL2.1 CBL1.1 | 2.54,50.8 RD2LD.2 | 2.54,50.8 2.54,54.61 RC1L.2 RL1L.2 | CBL3.1 2.54,41.91 2.54,50.8 | CBR1.1 CBR2.1 CBR3.1 86.36,38.1 | CB4.1 95.25,35.56 CBR1.1 | CB2.1 80.01,73.66 IC1.OUT | IC3.8 53.34,53.34 CB1.1 | 91.44,57.15 RC1R.2 97.79,54.61 97.79,50.8 | 91.44,57.15 RL1R.2 | 97.79,50.8 RD2RD.2 | 91.44,57.15 C3.+ | CBR1.1 97.79,41.91 97.79,50.8 | v73.66,13.97 76.2,16.51 82.55,16.51 82.55,29.21 83.82,30.48 83.82,35.56 86.36,38.1 | CB15.1 86.36,39.37 86.36,38.1
  Bottom 1.27: Q7R.E 67.31,3.81 68.58,2.54 RSZRT.2 80.01,2.54 85.09,7.62 86.36,7.62 CB11.1 | CB5.1 17.78,5.08 20.32,7.62 25.4,7.62 27.94,5.08 Q7L.E | 62.23,13.97 62.23,17.78 34.29,17.78 | 62.23,13.97 v62.23,11.43 | RSZLT.2 34.29,17.78 | 55.88,58.42 CB1.1 | 55.88,58.42 81.28,58.42 RL1R.2 | IC1.OUT 88.9,68.58 C3.+ | RL1L.2 19.05,58.42 24.13,58.42 | 55.88,58.42 24.13,58.42 | 62.23,13.97 v73.66,13.97 | 24.13,58.42 CB14.1 | 34.29,17.78 34.29,19.05 CB13.1
VPIN
  Top 1.27: D1.C 60.96,63.5 60.96,71.12 C1.+
  Bottom 1.27: IC1.IN 72.39,74.93 C1.+

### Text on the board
tPlace: Gilberd 20110805 | (c) 2011 rsw@jfet.org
